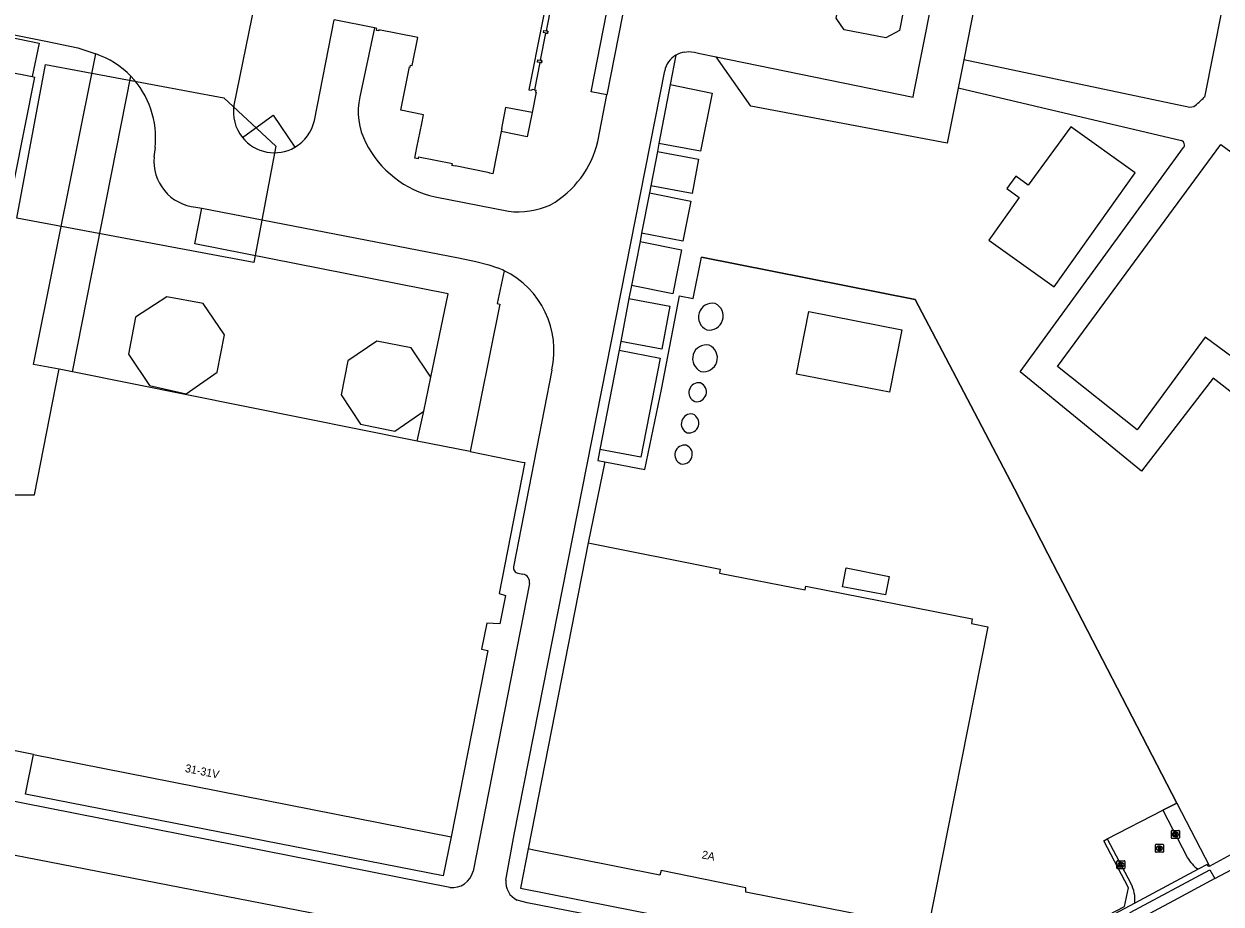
# Model space of a CAD drawing. Extents: x 158797 to 159887, y 384318 to 385255.
# Drawn here: x 159544.7 to 159694.3, y 384448.1 to 384558.1 of the extents above; entities that cross this region are included whole.
import ezdxf

# ---------------------------------------------------------------- set-up
doc = ezdxf.new("R2010")
doc.units = 0
for name, color, linetype in [('IMGEO_Erf', 7, 'Continuous'), ('IMGEO_Groenvoorziening', 7, 'Continuous'), ('IMGEO_Hek', 7, 'Continuous'), ('IMGEO_Kolk', 7, 'Continuous'), ('IMGEO_Muur', 7, 'Continuous'), ('IMGEO_Opslagtank', 7, 'Continuous'), ('IMGEO_Pand', 7, 'Continuous'), ('IMGEO_Pand_nummerreeks', 7, 'Continuous'), ('IMGEO_Pand_overbouw', 7, 'Continuous'), ('IMGEO_Pand_vergunning_verleend', 7, 'Continuous'), ('IMGEO_Parkeervlak_halfverhard', 7, 'Continuous'), ('IMGEO_Parkeervlak_open', 7, 'Continuous'), ('IMGEO_Rijbaan_lokaal_gesloten', 7, 'Continuous'), ('IMGEO_Rijbaan_lokaal_open', 7, 'Continuous'), ('IMGEO_Rioolput', 7, 'Continuous'), ('IMGEO_Voetpad_halfverhard', 7, 'Continuous'), ('IMGEO_Voetpad_open', 7, 'Continuous')]:
    doc.layers.add(name, color=color, linetype=linetype)

msp = doc.modelspace()

# ---------------------------------------------------------------- linework, layer by layer
at = {"layer": 'IMGEO_Erf'}
msp.add_lwpolyline([(159652.78, 384489.04), (159652.33, 384486.73), (159646.94, 384487.75), (159647.39, 384490.11), (159652.78, 384489.04)], dxfattribs=at)
at = {"layer": 'IMGEO_Groenvoorziening'}
for points in [[(159617.26, 384503.35), (159622.26, 384502.39), (159624.32, 384512.41), (159626.57, 384524.12), (159628.28, 384523.78), (159629.33, 384528.96), (159656.03, 384523.68), (159660.74, 384514.7), (159668.45, 384500), (159672.59, 384491.85), (159688.71, 384460.7)], [(159688.71, 384460.7), (159686.97, 384459.8)], [(159688.71, 384460.7), (159692.8, 384452.82)]]:
    msp.add_lwpolyline(points, dxfattribs=at)
at = {"layer": 'IMGEO_Hek'}
for points in [[(159672.59, 384491.85), (159668.45, 384500), (159660.74, 384514.7), (159656.03, 384523.68), (159629.33, 384528.96)], [(159686.97, 384459.8), (159688.71, 384460.7), (159672.59, 384491.85)], [(159680.01, 384456.2), (159686.97, 384459.8)]]:
    msp.add_lwpolyline(points, dxfattribs=at)
at = {"layer": 'IMGEO_Kolk'}
for p, q in [((159688.05, 384456.34), (159688.05, 384457.2)), ((159688.12, 384457.27), (159688.97, 384457.27)), ((159688.54, 384457.05), (159688.56, 384457.05)), ((159689.05, 384457.2), (159689.05, 384456.34)), ((159688.97, 384456.27), (159688.12, 384456.27)), ((159688.56, 384456.49), (159688.53, 384456.49)), ((159681.24, 384452.54), (159681.24, 384453.4)), ((159681.31, 384453.47), (159682.16, 384453.47)), ((159682.16, 384452.47), (159681.31, 384452.47)), ((159681.72, 384453.25), (159681.75, 384453.25)), ((159681.75, 384452.69), (159681.72, 384452.69)), ((159682.24, 384453.4), (159682.24, 384452.54))]:
    msp.add_line(p, q, dxfattribs=at)
for points in [[(159688.05, 384456.34), (159688.05, 384457.2)], [(159688.12, 384457.27), (159688.97, 384457.27)], [(159688.37, 384456.97), (159688.49, 384456.97), (159688.49, 384456.82), (159688.62, 384456.97), (159688.79, 384456.97), (159688.64, 384456.82), (159688.79, 384456.57), (159688.64, 384456.57), (159688.56, 384456.73), (159688.49, 384456.67), (159688.49, 384456.57), (159688.37, 384456.57), (159688.37, 384456.97)], [(159689.05, 384457.2), (159689.05, 384456.34)], [(159688.97, 384456.27), (159688.12, 384456.27)], [(159681.24, 384452.54), (159681.24, 384453.4)], [(159681.31, 384453.47), (159682.16, 384453.47)], [(159682.16, 384452.47), (159681.31, 384452.47)], [(159681.56, 384453.17), (159681.68, 384453.17), (159681.68, 384453.02), (159681.81, 384453.17), (159681.97, 384453.17), (159681.83, 384453.02), (159681.98, 384452.77), (159681.83, 384452.77), (159681.74, 384452.94), (159681.68, 384452.87), (159681.68, 384452.77), (159681.56, 384452.77), (159681.56, 384453.17)], [(159682.24, 384453.4), (159682.24, 384452.54)]]:
    msp.add_lwpolyline(points, dxfattribs=at)
for centre, start, end in [((159688.12, 384457.19), 91.552, 178.448), ((159688.12, 384457.19), 91.552, 178.448), ((159688.97, 384457.19), 1.552, 88.448), ((159688.97, 384457.19), 1.552, 88.448), ((159688.12, 384456.34), 181.552, 268.448), ((159688.12, 384456.34), 181.552, 268.448), ((159688.97, 384456.34), 271.552, 358.448), ((159688.97, 384456.34), 271.552, 358.448), ((159681.31, 384453.4), 91.552, 178.448), ((159681.31, 384453.4), 91.552, 178.448), ((159681.31, 384452.55), 181.552, 268.448), ((159681.31, 384452.55), 181.552, 268.448), ((159682.16, 384453.4), 1.552, 88.448), ((159682.16, 384453.4), 1.552, 88.448), ((159682.16, 384452.55), 271.552, 358.448), ((159682.16, 384452.55), 271.552, 358.448)]:
    msp.add_arc(centre, 0.0765, start, end, dxfattribs=at)
for centre, major_axis, ratio, start_param, end_param in [((159688.53, 384456.77), (-0.387, 0.002), 0.722429, 4.712389, 7.853982), ((159688.56, 384456.77), (-0.39, 0.002), 0.717154, 1.570796, 4.712389), ((159681.72, 384452.97), (-0.387, 0.002), 0.722429, 4.712389, 7.853982), ((159681.75, 384452.97), (-0.39, 0.002), 0.717154, 1.570796, 4.712389)]:
    msp.add_ellipse(centre, major_axis=major_axis, ratio=ratio, start_param=start_param, end_param=end_param, dxfattribs=at)
at = {"layer": 'IMGEO_Muur'}
msp.add_lwpolyline([(159527.56, 384536.87), (159530.86, 384554.5), (159536.35, 384553.4), (159545.66, 384551.55), (159545.95, 384551.49), (159540.8, 384525.69), (159539.2, 384526.01)], dxfattribs=at)
at = {"layer": 'IMGEO_Opslagtank'}
for centre, radius, start, end in [((159630.68, 384521.47), 1.73, 78.4106, 246.6651), ((159630.31, 384521.59), 1.74, 259.4454, 65.6303), ((159629.94, 384516.27), 1.73, 78.4549, 246.6208), ((159629.57, 384516.38), 1.74, 259.4454, 65.6303), ((159628.98, 384512.03), 1.23, 80.5927, 245.8327), ((159628.72, 384512.11), 1.22, 258.6023, 67.8231), ((159628.03, 384508.13), 1.23, 80.5833, 245.8873), ((159627.77, 384508.21), 1.22, 258.6299, 67.8407), ((159627.22, 384504.24), 1.22, 80.5211, 245.8907), ((159626.96, 384504.31), 1.22, 258.5665, 67.8453)]:
    msp.add_arc(centre, radius, start, end, dxfattribs=at)
at = {"layer": 'IMGEO_Pand'}
for points in [[(159593.86, 384602.88), (159597.78, 384602.1), (159596.3, 384594.68), (159601.06, 384593.73), (159601.11, 384593.98), (159601.61, 384593.89), (159601.55, 384593.63), (159608.22, 384592.3), (159608.3, 384592.71), (159608.89, 384592.59), (159608.81, 384592.19), (159615.89, 384590.78), (159607.76, 384549.9), (159608.13, 384549.83), (159608.16, 384549.97), (159608.42, 384549.92), (159608.41, 384549.9), (159608.48, 384549.89), (159608.64, 384549.85), (159608.6, 384549.61), (159608.68, 384549.59), (159608.17, 384547.04)], [(159588.44, 384557.64), (159583.43, 384558.63)], [(159604.29, 384544.67), (159603.24, 384539.39), (159602.84, 384539.47), (159602.85, 384539.53), (159598.56, 384540.39), (159598.55, 384540.33), (159598.14, 384540.41), (159598.17, 384540.52), (159598.19, 384540.63), (159593.95, 384541.45), (159593.93, 384541.36), (159593.91, 384541.25), (159593.51, 384541.33), (159593.77, 384542.68), (159594.37, 384545.66), (159594.59, 384546.77), (159591.75, 384547.33), (159592.83, 384552.75), (159592.9, 384552.73), (159592.95, 384552.98), (159593.17, 384552.93), (159593.86, 384556.43), (159589.02, 384557.39), (159588.99, 384557.26), (159588.69, 384557.32), (159588.74, 384557.58), (159588.44, 384557.64)], [(159609.62, 384557.33), (159609.95, 384557.26), (159610.11, 384557.23), (159610.06, 384556.95), (159609.89, 384556.98), (159609.57, 384557.04), (159609.62, 384557.33)], [(159609.38, 384553.55), (159609.33, 384553.27), (159609.16, 384553.3), (159608.83, 384553.36), (159608.89, 384553.65), (159609.21, 384553.59), (159609.38, 384553.55)], [(159608.17, 384547.04), (159604.84, 384547.7), (159604.31, 384545.06), (159604.37, 384545.05), (159604.29, 384544.67)], [(159564.92, 384511.89), (159568.79, 384514.6), (159569.7, 384519.23), (159567.04, 384523.15), (159562.49, 384524.01), (159558.61, 384521.44), (159557.7, 384516.83), (159560.35, 384512.91), (159564.92, 384511.89)], [(159641.19, 384514.35), (159642.73, 384522.16), (159654.35, 384519.89), (159652.8, 384512.06), (159641.19, 384514.35)], [(159595.48, 384513.95), (159593.05, 384517.62), (159588.75, 384518.45), (159585.12, 384515.99), (159584.31, 384511.74), (159586.7, 384508.06), (159591.01, 384507.21), (159594.62, 384509.72)], [(159545.84, 384466.78), (159534.72, 384468.97), (159539.36, 384492.01), (159541.18, 384491.64), (159541.21, 384491.78), (159541.3, 384491.76), (159541.89, 384494.71), (159541.8, 384494.72), (159541.83, 384494.85), (159539.1, 384495.4), (159539.97, 384499.85), (159543.04, 384499.23), (159545.96, 384499.26), (159549.01, 384514.8), (159549.04, 384514.96)], [(159550.7, 384514.63), (159549.04, 384514.96)], [(159593.79, 384505.97), (159550.7, 384514.63)], [(159594.62, 384509.72), (159595.48, 384513.95)], [(159600.42, 384504.64), (159593.79, 384505.97)], [(159600.42, 384504.64), (159606.93, 384503.33), (159607.25, 384503.27), (159607.21, 384503.1), (159604.03, 384486.9), (159604.83, 384486.65), (159604.14, 384483.12), (159603.29, 384483.16), (159602.48, 384483.19), (159601.84, 384479.93), (159602.62, 384479.78), (159602.2, 384477.63), (159598.04, 384456.49)], [(159615.17, 384493.22), (159631.65, 384489.94), (159631.59, 384489.43), (159642.3, 384487.34), (159642.37, 384487.83), (159663.17, 384483.74), (159663.06, 384483.15), (159665.1, 384482.72), (159657.65, 384445.04), (159634.86, 384449.54), (159634.88, 384450.1), (159624.28, 384452.24), (159624.12, 384451.68), (159608.37, 384454.81), (159607.65, 384454.95)], [(159615.17, 384493.22), (159607.65, 384454.95)], [(159545.84, 384466.78), (159598.04, 384456.49)]]:
    msp.add_lwpolyline(points, dxfattribs=at)
at = {"layer": 'IMGEO_Pand_overbouw'}
msp.add_lwpolyline([(159615.89, 384590.78), (159607.76, 384549.9), (159608.13, 384549.83), (159608.16, 384549.97), (159608.42, 384549.92), (159608.41, 384549.9), (159608.48, 384549.89), (159609.16, 384553.3), (159609.33, 384553.27), (159609.38, 384553.55), (159609.21, 384553.59), (159609.89, 384556.98), (159610.06, 384556.95), (159610.11, 384557.23), (159609.95, 384557.26), (159610.62, 384560.66)], dxfattribs=at)
at = {"layer": 'IMGEO_Pand_vergunning_verleend'}
msp.add_lwpolyline([(159547.36, 384553.07), (159569.65, 384548.89), (159576.13, 384542.83), (159573.4, 384528.28), (159543.75, 384533.84), (159547.36, 384553.07)], dxfattribs=at)
at = {"layer": 'IMGEO_Parkeervlak_halfverhard'}
for points in [[(159625.42, 384550.55), (159630.67, 384549.48), (159629.2, 384542.22), (159624, 384543.17)], [(159571.95, 384543.94), (159575.8, 384546.72), (159578.5, 384542.71)], [(159623.81, 384542.18), (159628.96, 384541.23), (159628.16, 384536.92), (159622.98, 384537.88)], [(159622.81, 384536.99), (159627.99, 384535.96), (159627, 384530.95), (159621.84, 384531.97)], [(159621.64, 384530.93), (159626.83, 384529.9), (159625.73, 384524.38), (159620.58, 384525.4)], [(159620.26, 384523.78), (159625.38, 384522.82), (159624.37, 384517.45), (159619.23, 384518.41)], [(159619.02, 384517.35), (159624.16, 384516.35), (159621.74, 384503.97), (159616.64, 384504.92)]]:
    msp.add_lwpolyline(points, dxfattribs=at)
at = {"layer": 'IMGEO_Parkeervlak_open'}
for points in [[(159687.99, 384709.81), (159693.36, 384713.16), (159693, 384711.1), (159662.09, 384553.66)], [(159661.38, 384550.08), (159661.02, 384548.24), (159660.04, 384543.22), (159635.49, 384547.85), (159631.17, 384554.03)]]:
    msp.add_lwpolyline(points, dxfattribs=at)
at = {"layer": 'IMGEO_Rijbaan_lokaal_gesloten'}
for points in [[(159683.16, 384708.36), (159683.17, 384708.15), (159683.17, 384707.52), (159683.62, 384707.43), (159654.08, 384557.3), (159652.34, 384556.38), (159647.17, 384557.4), (159646.14, 384558.86), (159676.23, 384712.08)], [(159631.17, 384554.03), (159655.77, 384548.99), (159655.81, 384549.27), (159668.22, 384611.89), (159675.67, 384649.86), (159687.36, 384709.41)], [(159625.25, 384588.73), (159617.51, 384549.27)], [(159516.94, 384562.1), (159547.37, 384555.96), (159551.38, 384555.15), (159553.62, 384554.38)], [(159573.47, 384560.62), (159570.89, 384547.99)], [(159580.96, 384546.07), (159583.43, 384558.63)], [(159588.44, 384557.64), (159586.61, 384549.01)], [(159627.24, 384554.62), (159627.69, 384554.69), (159628.43, 384554.59), (159629.13, 384554.45), (159631.17, 384554.03)], [(159604.87, 384451.05), (159605.92, 384456.77), (159624.73, 384552.25)], [(159616.36, 384543.42), (159617.51, 384549.27)], [(159561.03, 384542.67), (159560.9, 384541.51)], [(159596.03, 384536.49), (159605.19, 384534.7)], [(159566.12, 384535.23), (159566.87, 384535.08)], [(159566.87, 384535.08), (159598.95, 384528.87), (159601.12, 384528.43), (159602.74, 384528.02), (159603.84, 384527.64)], [(159610.62, 384514.85), (159605.84, 384490.25)], [(159606.39, 384489.43), (159607.01, 384489.31)], [(159607.82, 384488.14), (159600.79, 384452.18)], [(159597.88, 384450.13), (159504.38, 384468.61), (159503.48, 384468.8)], [(159502.14, 384462.21), (159586.21, 384445.87)], [(159693.47, 384451.24), (159699.77, 384454.61), (159703.8, 384456.78)], [(159693.47, 384451.24), (159688.29, 384448.47), (159683.47, 384445.89)], [(159649.71, 384438.71), (159650.02, 384439.92), (159607.52, 384448.23), (159606.27, 384448.55)]]:
    msp.add_lwpolyline(points, dxfattribs=at)
for centre, radius, start, end in [((159550.05, 384543.91), 11.06, 44.0374, 71.1457), ((159627.67, 384551.64), 3.01, 120.9705, 168.3458), ((159627.66, 384551.66), 2.98, 98.2345, 121.0601), ((159550.04, 384543.91), 11.06, 353.5278, 44.0333), ((159594.85, 384547.18), 8.43, 167.5016, 207.6327), ((159575.94, 384547.15), 5.12, 170.5745, 218.864), ((159575.94, 384547.16), 5.13, 299.888, 347.7803), ((159575.95, 384547.15), 5.13, 218.8579, 299.8584), ((159598.89, 384549.05), 12.88, 206.6341, 257.1597), ((159604.3, 384546.26), 12.39, 299.8842, 346.7758), ((159566.65, 384540.97), 5.77, 174.6667, 264.7593), ((159606.28, 384545.13), 10.49, 264.08, 293.582), ((159600.04, 384517.9), 10.45, 63.7163, 68.6922), ((159599.77, 384517.29), 11.12, 347.377, 63.8777), ((159606.53, 384490.12), 0.699, 168.89, 259.0359), ((159606.84, 384488.33), 1, 348.9807, 80.5513), ((159598.17, 384452.8), 2.69, 263.6196, 346.5728), ((159607.41, 384450.83), 2.55, 174.9526, 243.552)]:
    msp.add_arc(centre, radius, start, end, dxfattribs=at)
at = {"layer": 'IMGEO_Rijbaan_lokaal_open'}
for points in [[(159680.01, 384456.2), (159686.97, 384459.8)], [(159686.97, 384459.8), (159690.03, 384453.91)], [(159680.01, 384456.2), (159682.98, 384450.64)], [(159691.4, 384452.42), (159683.46, 384448.17)]]:
    msp.add_lwpolyline(points, dxfattribs=at)
for centre, radius, start, end in [((159693.84, 384456.03), 4.36, 209.2098, 235.9648), ((159679.39, 384448.66), 4.1, 353.117, 28.7782)]:
    msp.add_arc(centre, radius, start, end, dxfattribs=at)
at = {"layer": 'IMGEO_Rioolput'}
for p, q in [((159686.05, 384454.61), (159686.05, 384455.46)), ((159686.12, 384455.54), (159686.98, 384455.54)), ((159687.05, 384455.46), (159687.05, 384454.61)), ((159686.98, 384454.54), (159686.12, 384454.54)), ((159686.54, 384455.32), (159686.56, 384455.32)), ((159686.56, 384454.76), (159686.54, 384454.76))]:
    msp.add_line(p, q, dxfattribs=at)
for points in [[(159686.05, 384454.61), (159686.05, 384455.46)], [(159686.12, 384455.54), (159686.98, 384455.54)], [(159687.05, 384455.46), (159687.05, 384454.61)], [(159686.98, 384454.54), (159686.12, 384454.54)], [(159686.64, 384455.23), (159686.39, 384455.24), (159686.39, 384454.84)], [(159686.39, 384454.84), (159686.51, 384454.84), (159686.51, 384455), (159686.52, 384455)], [(159686.57, 384455.16), (159686.51, 384455.16), (159686.51, 384455.07)], [(159686.51, 384455.07), (159686.56, 384455.07)], [(159686.57, 384454.97), (159686.64, 384454.84), (159686.78, 384454.84), (159686.71, 384454.96)]]:
    msp.add_lwpolyline(points, dxfattribs=at)
for centre, radius, start, end in [((159686.13, 384455.46), 0.0765, 91.552, 178.448), ((159686.13, 384455.46), 0.0765, 91.552, 178.448), ((159686.97, 384455.46), 0.0765, 1.552, 88.448), ((159686.97, 384455.46), 0.0765, 1.552, 88.448), ((159686.13, 384454.61), 0.0765, 181.552, 268.448), ((159686.13, 384454.61), 0.0765, 181.552, 268.448), ((159686.52, 384454.95), 0.0533, 26.0293, 88.6989), ((159686.55, 384455.26), 0.19, 274.7715, 282.9687), ((159686.57, 384455.06), 0.0964, 77.0061, 93.1865), ((159686.59, 384455.12), 0.0378, 276.6634, 79.6772), ((159686.64, 384455.12), 0.109, 350.3612, 89.416), ((159686.64, 384455.12), 0.112, 277.5842, 350.9817), ((159686.62, 384454.91), 0.108, 29.5134, 73.7905), ((159686.97, 384454.61), 0.0765, 271.552, 358.448), ((159686.97, 384454.61), 0.0765, 271.552, 358.448)]:
    msp.add_arc(centre, radius, start, end, dxfattribs=at)
for centre, major_axis, ratio, start_param, end_param in [((159686.54, 384455.04), (-0.387, 0.002), 0.722429, 4.712389, 7.853982), ((159686.56, 384455.04), (-0.39, 0.002), 0.717154, 1.570796, 4.712389)]:
    msp.add_ellipse(centre, major_axis=major_axis, ratio=ratio, start_param=start_param, end_param=end_param, dxfattribs=at)
at = {"layer": 'IMGEO_Voetpad_halfverhard'}
for points in [[(159724.98, 384564.99), (159723.12, 384573.43), (159721.25, 384573.01), (159711.55, 384609.33), (159686.3, 384603.09), (159695.49, 384565.59), (159692.17, 384548.99)], [(159662.09, 384553.66), (159661.38, 384550.08)], [(159690.85, 384547.78), (159690.35, 384547.7), (159662.09, 384553.66)], [(159689.33, 384543.53), (159661.38, 384550.08)], [(159747.77, 384531.26), (159720.4, 384536.22), (159714.53, 384527.98), (159712.7, 384529.28), (159698.94, 384509.42), (159693.26, 384513.85), (159684.31, 384502.18), (159669.14, 384514.63), (159689.57, 384542.67)], [(159710.33, 384531.21), (159698.14, 384514.62), (159692.26, 384518.94), (159683.77, 384507.39), (159673.83, 384515.28), (159694.23, 384543.04), (159710.33, 384531.21)]]:
    msp.add_lwpolyline(points, dxfattribs=at)
for centre, radius, start, end in [((159684.74, 384555.81), 10.08, 307.2401, 317.4065), ((159689.12, 384543.01), 0.564, 322.4951, 68.2052)]:
    msp.add_arc(centre, radius, start, end, dxfattribs=at)
at = {"layer": 'IMGEO_Voetpad_open'}
for points in [[(159617.51, 384549.27), (159615.53, 384549.62), (159620.52, 384575.22), (159619.8, 384575.35), (159622.54, 384589.17), (159625.25, 384588.73)], [(159530.86, 384554.5), (159536.35, 384553.4), (159537.23, 384557.63), (159546.55, 384555.71), (159545.66, 384551.55), (159545.95, 384551.49), (159540.8, 384525.69), (159539.2, 384526.01)], [(159549.04, 384514.96), (159545.84, 384515.53), (159553.62, 384554.38)], [(159626.12, 384554.22), (159625.42, 384550.55)], [(159550.7, 384514.63), (159557.99, 384551.6)], [(159625.42, 384550.55), (159624, 384543.17)], [(159608.17, 384547.04), (159607.55, 384544.02), (159604.29, 384544.67)], [(159670.15, 384537.97), (159668.59, 384539.08), (159667.48, 384537.53), (159669.04, 384536.42), (159665.24, 384531.07), (159673.39, 384525.26), (159683.54, 384539.5), (159675.47, 384545.26), (159670.15, 384537.97)], [(159624, 384543.17), (159623.81, 384542.18)], [(159623.81, 384542.18), (159622.98, 384537.88)], [(159622.98, 384537.88), (159622.81, 384536.99)], [(159622.81, 384536.99), (159621.84, 384531.97)], [(159595.48, 384513.95), (159597.67, 384524.38), (159566, 384530.65), (159566.87, 384535.08)], [(159621.84, 384531.97), (159621.64, 384530.93)], [(159621.64, 384530.93), (159620.58, 384525.4)], [(159604.67, 384527.27), (159603.78, 384523.16), (159604.11, 384523.09), (159600.42, 384504.64)], [(159620.58, 384525.4), (159620.26, 384523.78)], [(159620.26, 384523.78), (159619.23, 384518.41)], [(159619.23, 384518.41), (159619.02, 384517.35)], [(159619.02, 384517.35), (159616.64, 384504.92)], [(159593.79, 384505.97), (159594.62, 384509.72)], [(159692.8, 384452.82), (159696.01, 384454.54), (159703.25, 384458.43), (159703.42, 384458.15), (159750.19, 384483.21), (159760.8, 384488.7), (159782.83, 384500.11), (159795.21, 384506.59)], [(159616.64, 384504.92), (159616.36, 384503.52), (159617.26, 384503.35)], [(159617.26, 384503.35), (159615.17, 384493.22)], [(159598.04, 384456.49), (159597.03, 384451.58), (159544.83, 384461.81), (159545.84, 384466.78)], [(159607.65, 384454.95), (159606.69, 384450.05), (159650.34, 384441.44), (159664.68, 384438.64), (159682.17, 384447.75), (159682.7, 384450.09), (159679.6, 384455.98), (159680.01, 384456.2)], [(159692.8, 384452.82), (159692.66, 384452.75), (159692.5, 384453.02), (159691.4, 384452.42)], [(159683.47, 384445.89), (159682.88, 384447.01), (159692.87, 384452.35), (159693.47, 384451.24)], [(159683.46, 384448.17), (159666.37, 384439.04), (159655.5, 384433.22)]]:
    msp.add_lwpolyline(points, dxfattribs=at)

# ---------------------------------------------------------------- texts
at = {"layer": 'IMGEO_Pand_nummerreeks'}
for s, rotation, p in [('31-31V', 348.6497, (159564.72, 384464.6)), ('2A', 348.5706, (159629.29, 384453.8))]:
    msp.add_text(s, height=1, rotation=rotation, dxfattribs=at).set_placement(p)

doc.saveas('drawing.dxf')
